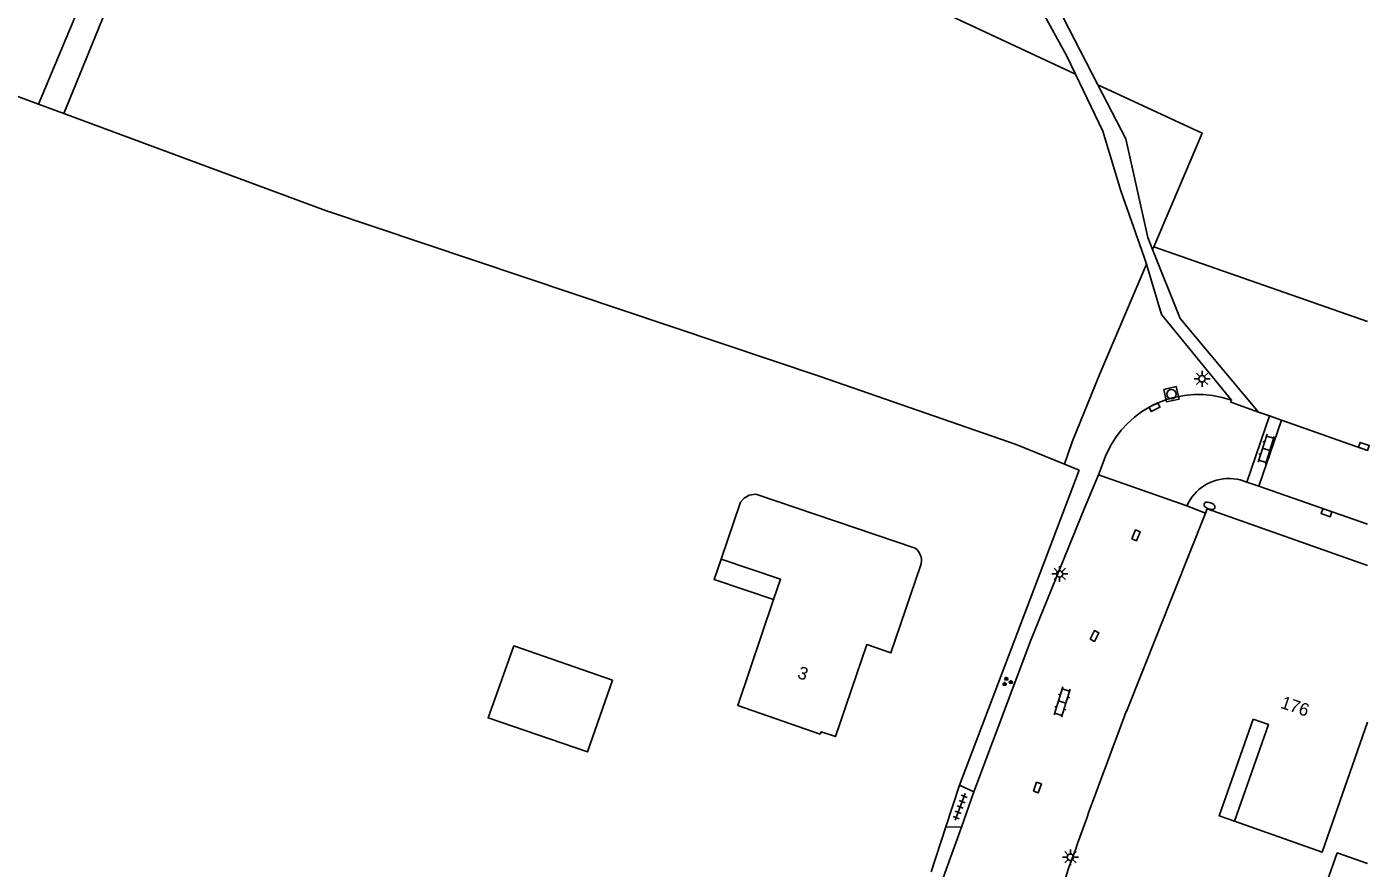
# Model space of a CAD drawing. Extents: x 128999 to 131010, y 395498 to 399007.
# Drawn here: x 130894.7 to 131000.1, y 396903.1 to 396969.2 of the extents above; entities that cross this region are included whole.
import ezdxf

# ---------------------------------------------------------------- set-up
doc = ezdxf.new("R2010")
doc.units = 0
for name, color, linetype in [('gg-afsc-erfafscheiding', 7, 'Continuous'), ('gg-afsc-hekwerk', 7, 'Continuous'), ('gg-anno-huisnummerreeks BGT', 7, 'Continuous'), ('gg-bbg-gedigitaliseerde bebouwing', 7, 'Continuous'), ('gg-bbg-gedigitaliseerde bijgebouw', 7, 'Continuous'), ('gg-bbg-hoofdgebouw', 7, 'Continuous'), ('gg-bbg-luifel en loopbrug', 7, 'Continuous'), ('gg-knt-onverhard', 7, 'Continuous'), ('gg-knt-verharding', 7, 'Continuous'), ('gt-grn-groengrens', 7, 'Continuous'), ('gt-grn-weggrens', 7, 'Continuous'), ('gt-symb-brandkraan', 7, 'Continuous'), ('gt-symb-groenvak', 7, 'Continuous'), ('gt-symb-klinker verharding', 7, 'Continuous'), ('gt-symb-kolk', 7, 'Continuous'), ('gt-symb-kolk center center', 7, 'Continuous'), ('gt-symb-lichtmast', 7, 'Continuous'), ('gt-symb-rioolschacht', 7, 'Continuous'), ('gt-symb-tegel verharding', 7, 'Continuous')]:
    doc.layers.add(name, color=color, linetype=linetype)

# ---------------------------------------------------------------- blocks, each defined once
blk = doc.blocks.new('gt0-KL1')
at = {"layer": 'gt-symb-klinker verharding'}
for p, q in [((-1.15, 0.3), (1.15, 0.3)), ((-1, -0.3), (-1, 0.3)), ((-0.5, 0.3), (-0.5, 0.45)), ((0, -0.3), (0, 0.3)), ((0.5, 0.3), (0.5, 0.45)), ((1, -0.3), (1, 0.3)), ((-1.15, -0.3), (1.15, -0.3)), ((-0.5, -0.45), (-0.5, -0.3)), ((0.5, -0.45), (0.5, -0.3))]:
    blk.add_line(p, q, dxfattribs=at)
blk = doc.blocks.new('gt0-KOLK')
at = {"layer": 'gt-symb-kolk'}
blk.add_lwpolyline([(0, 0), (0.38, 0), (0.38, 0.4), (-0.38, 0.4), (-0.38, 0), (0, 0)], dxfattribs=at)
blk = doc.blocks.new('gt0-RS')
at = {"layer": 'gt-symb-rioolschacht'}
blk.add_lwpolyline([(-0.5, -0.5), (0.5, -0.5), (0.5, 0.5), (-0.5, 0.5)], close=True, dxfattribs=at)
blk.add_circle((0, 0), 0.375, dxfattribs=at)
blk = doc.blocks.new('gt0-LMAST')
at = {"layer": 'gt-symb-lichtmast'}
for p, q in [((-0.18, 0.17), (-0.45, 0.44)), ((-0.01, 0.25), (-0.01, 0.62)), ((0.17, 0.17), (0.44, 0.44)), ((-0.26, 0), (-0.63, 0)), ((-0.18, -0.18), (-0.45, -0.45)), ((-0.01, -0.25), (-0.01, -0.63)), ((0.44, -0.45), (0.17, -0.18)), ((0.24, 0), (0.62, 0))]:
    blk.add_line(p, q, dxfattribs=at)
blk.add_circle((-0.01, 0), 0.25, dxfattribs=at)
blk = doc.blocks.new('gt0-BR')
at = {"layer": 'gt-symb-brandkraan'}
for centre, radius, start, end in [((-0.24, 0), 0.206, 107.5669, 252.4331), ((0.6, -2.66), 3, 106.892, 107.5669), ((0, -0.69), 0.938, 73.108, 106.892), ((-0.6, -2.66), 3, 72.4331, 73.108), ((0.24, 0), 0.206, 287.567, 72.4331), ((0.6, 2.66), 3, 252.4331, 253.108), ((0, 0.69), 0.938, 253.108, 286.8921), ((-0.6, 2.66), 3, 286.8921, 287.567)]:
    blk.add_arc(centre, radius, start, end, dxfattribs=at)
blk = doc.blocks.new('gt0-GRVAK')
at = {"layer": 'gt-symb-groenvak'}
for p, q in [((-0.11, 0.19), (-0.23, 0.24)), ((-0.18, 0.15), (0.09, 0.15)), ((-0.09, 0.21), (-0.16, 0.32)), ((-0.05, 0.21), (-0.05, 0.39)), ((0, 0.21), (0.06, 0.32)), ((0.01, 0.19), (0.13, 0.24)), ((0.26, -0.05), (0.2, 0.06)), ((0.31, -0.05), (0.31, 0.13)), ((0.35, -0.05), (0.41, 0.06)), ((-0.24, -0.23), (-0.36, -0.18)), ((-0.32, -0.26), (-0.05, -0.26)), ((-0.23, -0.21), (-0.29, -0.1)), ((-0.18, -0.2), (-0.18, -0.02)), ((-0.14, -0.21), (-0.07, -0.1)), ((-0.12, -0.23), (0, -0.18)), ((0.24, -0.07), (0.12, -0.02)), ((0.17, -0.11), (0.44, -0.11)), ((0.37, -0.07), (0.49, -0.02))]:
    blk.add_line(p, q, dxfattribs=at)
blk = doc.blocks.new('gt0-KOLKCC')
at = {"layer": 'gt-symb-kolk center center'}
blk.add_lwpolyline([(-0.38, 0.2), (0.37, 0.2), (0.37, -0.2), (-0.38, -0.2)], close=True, dxfattribs=at)
blk = doc.blocks.new('gt0-TEG1')
at = {"layer": 'gt-symb-tegel verharding'}
for p, q in [((-1.12, 0), (1.12, 0)), ((-0.9, -0.25), (-0.9, 0.25)), ((-0.45, -0.25), (-0.45, 0.25)), ((0, -0.25), (0, 0.25)), ((0.45, -0.25), (0.45, 0.25)), ((0.9, -0.25), (0.9, 0.25))]:
    blk.add_line(p, q, dxfattribs=at)

msp = doc.modelspace()

# ---------------------------------------------------------------- linework, layer by layer
at = {"layer": 'gg-afsc-erfafscheiding'}
msp.add_line((130967.97, 396909.58), (130977.37, 396934.33), dxfattribs=at)
at = {"layer": 'gg-afsc-hekwerk'}
for p, q in [((130893.79, 396963.77), (130895.62, 396963.09)), ((130895.62, 396963.09), (130897.6, 396962.35))]:
    msp.add_line(p, q, dxfattribs=at)
msp.add_lwpolyline([(130897.6, 396962.35), (130918.17, 396954.73), (130957.03, 396941.68), (130972.42, 396936.36)], dxfattribs=at)
at = {"layer": 'gg-bbg-gedigitaliseerde bebouwing'}
for points in [[(130964.47, 396928.21), (130951.97, 396932.44), (130951.43, 396932.36), (130951.06, 396932.14), (130950.76, 396931.81), (130949.23, 396927.34)], [(130949.23, 396927.34), (130953.91, 396925.78), (130953.36, 396924.16)], [(130953.36, 396924.16), (130950.55, 396915.83), (130957.03, 396913.59)]]:
    msp.add_lwpolyline(points, dxfattribs=at)
at = {"layer": 'gg-bbg-gedigitaliseerde bijgebouw'}
for points in [[(130940.7, 396917.83), (130938.75, 396912.19), (130930.94, 396914.86), (130932.95, 396920.52), (130940.7, 396917.83)], [(131000, 396903.43), (130997.63, 396904.26), (130995.28, 396897.58), (130998.92, 396896.3), (131000, 396899.37)]]:
    msp.add_lwpolyline(points, dxfattribs=at)
at = {"layer": 'gg-bbg-hoofdgebouw'}
for points in [[(130957.03, 396913.59), (130957.1, 396913.78), (130958.21, 396913.4), (130960.69, 396920.64), (130962.56, 396919.97), (130964.9, 396926.81)], [(130991.04, 396914.77), (130992.23, 396914.35), (130989.56, 396906.75)], [(130989.56, 396906.75), (130996.45, 396904.33), (131000, 396914.52)]]:
    msp.add_lwpolyline(points, dxfattribs=at)
msp.add_arc((130963.8, 396927.24), 1.18, 338.6374, 55.5105, dxfattribs=at)
at = {"layer": 'gg-bbg-luifel en loopbrug'}
for points in [[(130949.23, 396927.34), (130948.69, 396925.75), (130953.36, 396924.16)], [(130989.56, 396906.75), (130988.37, 396907.17), (130991.04, 396914.77)]]:
    msp.add_lwpolyline(points, dxfattribs=at)
at = {"layer": 'gg-knt-onverhard'}
for p, q in [((130904.6, 396979.49), (130897.6, 396962.35)), ((130902.17, 396978.78), (130895.62, 396963.09))]:
    msp.add_line(p, q, dxfattribs=at)
for points in [[(130962.63, 396999.41), (130971.96, 396974.94), (130976.37, 396966.91), (130977.08, 396965.44)], [(130978.84, 396964.62), (130972.91, 396976.13), (130964.36, 396998.82)], [(130977.08, 396965.44), (130979.23, 396960.96), (130980.63, 396956.28), (130982.47, 396951.08), (130982.64, 396950.51)], [(130983.13, 396951.66), (130982.76, 396952.6), (130981.03, 396960.37), (130978.84, 396964.62)], [(130983.13, 396951.66), (130985.29, 396946.25), (130991.44, 396938.9)], [(130982.64, 396950.51), (130983.84, 396946.57), (130989.32, 396939.83)]]:
    msp.add_lwpolyline(points, dxfattribs=at)
at = {"layer": 'gg-knt-verharding'}
for p, q in [((130990.52, 396933.39), (130992.31, 396938.59)), ((130991.44, 396938.9), (130992.31, 396938.59)), ((130991.47, 396933.07), (130993.25, 396938.26)), ((130992.31, 396938.59), (130993.25, 396938.26)), ((130993.25, 396938.26), (131000, 396935.89)), ((130978.88, 396933.96), (130979.49, 396935.55)), ((130990.52, 396933.39), (130990.01, 396933.57)), ((130991.47, 396933.07), (130990.52, 396933.39)), ((130991.47, 396933.07), (131000, 396930.08)), ((130981.07, 396915.36), (130987.28, 396930.96)), ((130987.28, 396930.96), (130985.83, 396931.53)), ((130969.1, 396909.07), (130967.97, 396909.58)), ((130968.11, 396906.28), (130969.1, 396909.07)), ((130968.11, 396906.28), (130966.9, 396906.31))]:
    msp.add_line(p, q, dxfattribs=at)
for points in [[(130989.32, 396939.83), (130989.27, 396939.67), (130991.44, 396938.9)], [(130969.1, 396909.07), (130973.57, 396920.97), (130977.77, 396931.34), (130978.88, 396933.96)], [(130985.83, 396931.53), (130986.01, 396931.88), (130986.21, 396932.22)], [(130987.28, 396930.96), (130987.42, 396931.3), (131000, 396926.83)], [(130964.48, 396895.57), (130966.82, 396902.66), (130968.11, 396906.28)]]:
    msp.add_lwpolyline(points, dxfattribs=at)
for centre, radius, start, end in [((130986.69, 396932.44), 7.84, 70.3984, 156.6694), ((130989.13, 396930.04), 3.64, 75.9281, 143.2651), ((131559.64, 396695.67), 618.88, 159.20791, 160.76474)]:
    msp.add_arc(centre, radius, start, end, dxfattribs=at)
at = {"layer": 'gt-grn-groengrens'}
for p, q in [((130983.22, 396951.87), (130983.13, 396951.66)), ((130983.22, 396951.87), (131000, 396946)), ((130972.42, 396936.36), (130976.22, 396934.8)), ((130976.22, 396934.8), (130977.37, 396934.33)), ((130965.73, 396902.76), (130966.9, 396906.31))]:
    msp.add_line(p, q, dxfattribs=at)
for points in [[(130930.31, 397010.47), (130923.17, 396990.65), (130977.08, 396965.44)], [(130978.84, 396964.62), (130987.02, 396960.8), (130983.22, 396951.87)], [(130982.64, 396950.51), (130978.99, 396941.91), (130976.8, 396936.55), (130976.22, 396934.8)]]:
    msp.add_lwpolyline(points, dxfattribs=at)
at = {"layer": 'gt-grn-weggrens'}
for p, q in [((130978.88, 396933.96), (130985.83, 396931.53)), ((130966.9, 396906.31), (130967.97, 396909.58))]:
    msp.add_line(p, q, dxfattribs=at)

# ---------------------------------------------------------------- block references
at = {"layer": 'gt-symb-brandkraan', "rotation": 159.33669709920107}
msp.add_blockref('gt0-BR', (130987.6, 396931.53), dxfattribs=at)
at = {"layer": 'gt-symb-groenvak'}
msp.add_blockref('gt0-GRVAK', (130971.69, 396917.71), dxfattribs=at)
at = {"layer": 'gt-symb-klinker verharding'}
for p, rotation in [((130992.06, 396935.97), 72.59811208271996), ((130976.02, 396916.11), -107.14904389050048)]:
    msp.add_blockref('gt0-KL1', p, dxfattribs=dict(at, rotation=rotation))
at = {"layer": 'gt-symb-kolk'}
for p, rotation in [((130983.19, 396939.46), -153.5118214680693), ((130999.65, 396936.01), -19.322482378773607), ((130996.86, 396931.18), 160.67751762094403)]:
    msp.add_blockref('gt0-KOLK', p, dxfattribs=dict(at, rotation=rotation))
at = {"layer": 'gt-symb-kolk center center'}
for p, rotation in [((130981.83, 396929.22), 66.86909051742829), ((130978.57, 396921.31), 63.12746100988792), ((130974.09, 396909.4), 70.73158503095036)]:
    msp.add_blockref('gt0-KOLKCC', p, dxfattribs=dict(at, rotation=rotation))
at = {"layer": 'gt-symb-lichtmast'}
for p in [(130987.02, 396941.51), (130975.84, 396926.18), (130976.68, 396903.92)]:
    msp.add_blockref('gt0-LMAST', p, dxfattribs=at)
at = {"layer": 'gt-symb-rioolschacht', "rotation": -77.29726808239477}
msp.add_blockref('gt0-RS', (130984.61, 396940.3), dxfattribs=at)
at = {"layer": 'gt-symb-tegel verharding', "rotation": 69.20927472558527}
msp.add_blockref('gt0-TEG1', (130968.02, 396907.87), dxfattribs=at)

# ---------------------------------------------------------------- texts
at = {"layer": 'gg-anno-huisnummerreeks BGT'}
for s, rotation, p in [('3', 341.1, (130955.16, 396918.02)), ('176', 341.2, (130993.11, 396915.67))]:
    msp.add_text(s, height=1, rotation=rotation, dxfattribs=at).set_placement(p)

doc.saveas('drawing.dxf')
